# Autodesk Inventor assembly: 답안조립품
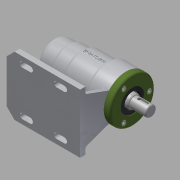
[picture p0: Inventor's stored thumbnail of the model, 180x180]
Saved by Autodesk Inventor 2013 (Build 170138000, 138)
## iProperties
Created: 2017-09
Part Number: 답안조립품
Document SubType Name: Assembly
Designer: Windows7
Author: Windows7
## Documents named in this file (9)
- C:\Users\Windows7\Desktop\470908V1012\답안조립품.iam
- C:\Users\Windows7\Desktop\470908V1012\축.ipt
- C:\Users\Windows7\Desktop\470908V1012\베어링 6004.ipt
- C:\Users\Windows7\Desktop\470908V1012\어댑터슬리브.ipt
- C:\Users\Windows7\Desktop\470908V1012\볼트 M4 x 12.ipt
- C:\Users\Windows7\Desktop\470908V1012\베어링 51202.ipt
- C:\Users\Windows7\Desktop\470908V1012\본체.ipt
- C:\Users\Windows7\Desktop\470908V1012\커버.ipt
- C:\Users\Windows7\Desktop\470908V1012\오일 실 20x35x7.ipt
